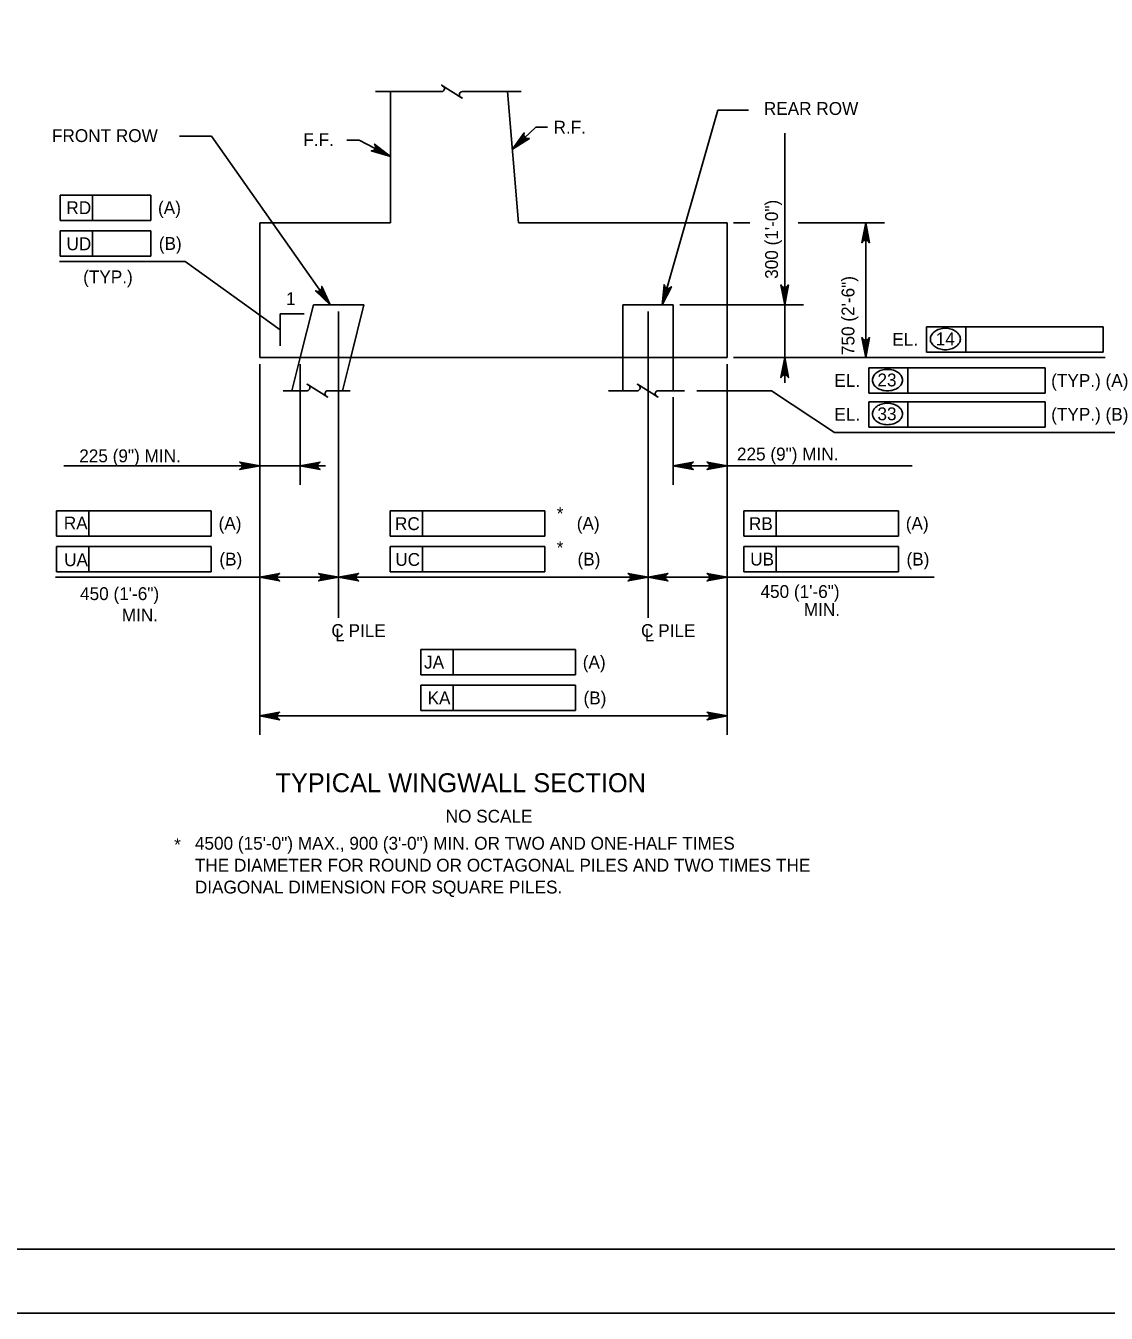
# Model space of a CAD drawing. Extents: x 638340 to 640241, y 295465 to 298435.
# Drawn here: x 639649.8 to 639902.2, y 295465.5 to 295766.2 of the extents above; entities that cross this region are included whole.
import ezdxf

# ---------------------------------------------------------------- set-up
doc = ezdxf.new("R2010")
doc.units = 0
for name, color, linetype in [('2', 7, 'Continuous'), ('4', 7, 'Continuous'), ('5', 7, 'Continuous'), ('PLT-BNDY', 7, 'Continuous')]:
    doc.layers.add(name, color=color, linetype=linetype)

msp = doc.modelspace()

# ---------------------------------------------------------------- linework, layer by layer
at = {"layer": '2'}
for p, q in [((639811.41, 295746.46), (639818.61, 295746.46)), ((639693.2, 295740.4), (639685.68, 295740.4)), ((639763.45, 295737.34), (639768.92, 295742.5)), ((639768.92, 295742.5), (639771.65, 295742.5)), ((639827.06, 295700.99), (639827.06, 295741.12)), ((639727.65, 295739.45), (639724.8, 295739.45)), ((639735.01, 295735.64), (639727.65, 295739.45)), ((639657.85, 295726.65), (639678.98, 295726.65)), ((639657.85, 295726.65), (639657.85, 295720.75)), ((639665.41, 295726.65), (639665.41, 295720.75)), ((639678.98, 295726.65), (639678.98, 295720.75)), ((639657.85, 295720.75), (639678.98, 295720.75)), ((639815.13, 295720.19), (639818.94, 295720.19)), ((639830.2, 295720.19), (639850.41, 295720.19)), ((639845.98, 295720.19), (639845.98, 295688.69)), ((639657.85, 295718.3), (639657.85, 295712.39)), ((639657.85, 295718.3), (639678.98, 295718.3)), ((639665.41, 295718.3), (639665.41, 295712.39)), ((639678.98, 295718.3), (639678.98, 295712.39)), ((639687.03, 295711.12), (639657.69, 295711.12)), ((639657.85, 295712.39), (639678.98, 295712.39)), ((639709.25, 295695.16), (639687.03, 295711.12)), ((639802.58, 295700.99), (639831.49, 295700.99)), ((639827.06, 295700.99), (639827.06, 295688.69)), ((639709.25, 295698.91), (639709.25, 295691.41)), ((639714.81, 295698.91), (639709.25, 295698.91)), ((639722.86, 295699.45), (639722.86, 295627.87)), ((639722.86, 295699.45), (639722.86, 295627.87)), ((639795.14, 295699.45), (639795.14, 295627.87)), ((639860.22, 295695.88), (639901.43, 295695.88)), ((639860.22, 295689.97), (639860.22, 295695.88)), ((639869.39, 295689.97), (639869.39, 295695.88)), ((639901.43, 295695.88), (639901.43, 295689.97)), ((639815.13, 295688.69), (639901.9, 295688.69)), ((639815.13, 295688.69), (639831.49, 295688.69)), ((639827.06, 295688.69), (639827.06, 295682.79)), ((639901.43, 295689.97), (639860.22, 295689.97)), ((639704.43, 295687.15), (639704.43, 295624.32)), ((639704.43, 295687.15), (639704.43, 295600.54)), ((639704.43, 295687.15), (639704.43, 295659)), ((639713.88, 295687.15), (639713.88, 295659)), ((639813.59, 295687.15), (639813.59, 295624.32)), ((639813.59, 295687.15), (639813.59, 295600.54)), ((639813.59, 295687.15), (639813.59, 295659)), ((639846.69, 295680.37), (639846.69, 295686.28)), ((639846.69, 295686.28), (639887.9, 295686.28)), ((639855.86, 295680.37), (639855.86, 295686.28)), ((639887.9, 295686.28), (639887.9, 295680.37)), ((639801.04, 295679.42), (639801.04, 295659)), ((639806.54, 295680.96), (639824.01, 295680.96)), ((639824.01, 295680.96), (639838.69, 295671.18)), ((639887.9, 295680.37), (639846.69, 295680.37)), ((639846.69, 295678.37), (639887.9, 295678.37)), ((639846.69, 295672.46), (639846.69, 295678.37)), ((639855.86, 295672.46), (639855.86, 295678.37)), ((639887.9, 295678.37), (639887.9, 295672.46)), ((639838.69, 295671.18), (639912.2, 295671.18)), ((639887.9, 295672.46), (639846.69, 295672.46)), ((639713.88, 295663.43), (639658.65, 295663.43)), ((639713.88, 295663.43), (639719.79, 295663.43)), ((639801.04, 295663.43), (639813.59, 295663.43)), ((639813.59, 295663.43), (639856.81, 295663.43)), ((639656.99, 295652.92), (639693.12, 295652.92)), ((639656.99, 295652.92), (639656.99, 295647.01)), ((639664.55, 295652.92), (639664.55, 295647.01)), ((639693.12, 295652.92), (639693.12, 295647.01)), ((639734.89, 295652.92), (639771.03, 295652.92)), ((639734.89, 295652.92), (639734.89, 295647.01)), ((639742.45, 295652.92), (639742.45, 295647.01)), ((639771.03, 295652.92), (639771.03, 295647.01)), ((639817.5, 295652.92), (639853.64, 295652.92)), ((639817.5, 295652.92), (639817.5, 295647.01)), ((639825.07, 295652.92), (639825.07, 295647.01)), ((639853.64, 295652.92), (639853.64, 295647.01)), ((639656.99, 295647.01), (639693.12, 295647.01)), ((639734.89, 295647.01), (639771.03, 295647.01)), ((639817.5, 295647.01), (639853.64, 295647.01)), ((639656.99, 295644.57), (639693.12, 295644.57)), ((639656.99, 295644.57), (639656.99, 295638.66)), ((639664.55, 295644.57), (639664.55, 295638.66)), ((639693.12, 295644.57), (639693.12, 295638.66)), ((639734.89, 295644.57), (639771.03, 295644.57)), ((639734.89, 295644.57), (639734.89, 295638.66)), ((639742.45, 295644.57), (639742.45, 295638.66)), ((639771.03, 295644.57), (639771.03, 295638.66)), ((639813.59, 295645.92), (639813.59, 295625.79)), ((639817.5, 295644.57), (639853.64, 295644.57)), ((639817.5, 295644.57), (639817.5, 295638.66)), ((639825.07, 295644.57), (639825.07, 295638.66)), ((639853.64, 295644.57), (639853.64, 295638.66)), ((639722.86, 295640.9), (639722.86, 295632.96)), ((639795.14, 295640.9), (639795.14, 295632.96)), ((639704.43, 295637.39), (639656.72, 295637.39)), ((639656.99, 295638.66), (639693.12, 295638.66)), ((639719.91, 295637.39), (639704.43, 295637.39)), ((639725.82, 295637.39), (639792.18, 295637.39)), ((639734.89, 295638.66), (639771.03, 295638.66)), ((639798.09, 295637.39), (639813.59, 295637.39)), ((639813.59, 295637.39), (639861.99, 295637.39)), ((639817.5, 295638.66), (639853.64, 295638.66)), ((639742.05, 295620.5), (639778.18, 295620.5)), ((639742.05, 295620.5), (639742.05, 295614.59)), ((639749.61, 295620.5), (639749.61, 295614.59)), ((639778.18, 295620.5), (639778.18, 295614.59)), ((639742.05, 295614.59), (639778.18, 295614.59)), ((639742.05, 295612.15), (639778.18, 295612.15)), ((639742.05, 295612.15), (639742.05, 295606.24)), ((639749.61, 295612.15), (639749.61, 295606.24)), ((639778.18, 295612.15), (639778.18, 295606.24)), ((639704.43, 295602.46), (639704.43, 295607.47)), ((639813.59, 295607.47), (639813.59, 295602.46)), ((639704.43, 295604.97), (639813.59, 295604.97)), ((639742.05, 295606.24), (639778.18, 295606.24)), ((640102.46, 295480.46), (639316.46, 295480.46))]:
    msp.add_line(p, q, dxfattribs=at)
for points in [[(639798.48, 295700.99), (639811.41, 295746.46)], [(639720.9, 295700.99), (639693.2, 295740.4)], [(639763.45, 295737.34), (639766.24, 295741.17), (639766.15, 295740.74), (639766.23, 295740.39), (639766.4, 295740.13), (639766.66, 295739.94), (639767.01, 295739.84), (639767.44, 295739.9), (639763.45, 295737.34), (639767.01, 295739.84), (639766.66, 295739.94), (639763.45, 295737.34), (639766.4, 295740.13), (639766.23, 295740.39), (639763.45, 295737.34), (639766.15, 295740.74)], [(639735.01, 295735.64), (639730.47, 295737.01), (639730.9, 295737.07), (639731.21, 295737.26), (639731.4, 295737.51), (639731.5, 295737.81), (639731.48, 295738.18), (639731.27, 295738.56), (639735.01, 295735.64), (639731.48, 295738.18), (639731.5, 295737.81), (639735.01, 295735.64), (639731.4, 295737.51), (639731.21, 295737.26), (639735.01, 295735.64), (639730.9, 295737.07)], [(639845.98, 295720.19), (639846.85, 295715.53), (639846.6, 295715.89), (639846.29, 295716.07), (639845.98, 295716.13), (639845.66, 295716.07), (639845.35, 295715.89), (639845.1, 295715.53), (639845.98, 295720.19), (639845.35, 295715.89), (639845.66, 295716.07), (639845.98, 295720.19), (639845.98, 295716.13), (639846.29, 295716.07), (639845.98, 295720.19), (639846.6, 295715.89)], [(639720.9, 295700.99), (639717.5, 295704.3), (639717.91, 295704.15), (639718.28, 295704.18), (639718.56, 295704.31), (639718.79, 295704.54), (639718.94, 295704.87), (639718.93, 295705.31), (639720.9, 295700.99), (639718.94, 295704.87), (639718.79, 295704.54), (639720.9, 295700.99), (639718.56, 295704.31), (639718.28, 295704.18), (639720.9, 295700.99), (639717.91, 295704.15)], [(639798.48, 295700.99), (639798.91, 295705.71), (639799.06, 295705.3), (639799.31, 295705.03), (639799.59, 295704.9), (639799.91, 295704.86), (639800.26, 295704.96), (639800.6, 295705.23), (639798.48, 295700.99), (639800.26, 295704.96), (639799.91, 295704.86), (639798.48, 295700.99), (639799.59, 295704.9), (639799.31, 295705.03), (639798.48, 295700.99), (639799.06, 295705.3)], [(639827.06, 295700.99), (639826.18, 295705.65), (639826.43, 295705.29), (639826.74, 295705.11), (639827.06, 295705.05), (639827.37, 295705.11), (639827.68, 295705.29), (639827.93, 295705.65), (639827.06, 295700.99), (639827.68, 295705.29), (639827.37, 295705.11), (639827.06, 295700.99), (639827.06, 295705.05), (639826.74, 295705.11), (639827.06, 295700.99), (639826.43, 295705.29)], [(639845.98, 295688.69), (639845.1, 295693.35), (639845.35, 295692.99), (639845.66, 295692.81), (639845.98, 295692.75), (639846.29, 295692.81), (639846.6, 295692.99), (639846.85, 295693.35), (639845.98, 295688.69), (639846.6, 295692.99), (639846.29, 295692.81), (639845.98, 295688.69), (639845.98, 295692.75), (639845.66, 295692.81), (639845.98, 295688.69), (639845.35, 295692.99)], [(639827.06, 295688.69), (639827.93, 295684.03), (639827.68, 295684.39), (639827.37, 295684.57), (639827.06, 295684.63), (639826.74, 295684.57), (639826.43, 295684.39), (639826.18, 295684.03), (639827.06, 295688.69), (639826.43, 295684.39), (639826.74, 295684.57), (639827.06, 295688.69), (639827.06, 295684.63), (639827.37, 295684.57), (639827.06, 295688.69), (639827.68, 295684.39)], [(639704.43, 295663.43), (639699.77, 295662.55), (639700.13, 295662.8), (639700.31, 295663.11), (639700.37, 295663.43), (639700.31, 295663.74), (639700.13, 295664.05), (639699.77, 295664.3), (639704.43, 295663.43), (639700.13, 295664.05), (639700.31, 295663.74), (639704.43, 295663.43), (639700.37, 295663.43), (639700.31, 295663.11), (639704.43, 295663.43), (639700.13, 295662.8)], [(639713.88, 295663.43), (639718.54, 295664.3), (639718.18, 295664.05), (639718, 295663.74), (639717.94, 295663.43), (639718, 295663.11), (639718.18, 295662.8), (639718.54, 295662.55), (639713.88, 295663.43), (639718.18, 295662.8), (639718, 295663.11), (639713.88, 295663.43), (639717.94, 295663.43), (639718, 295663.74), (639713.88, 295663.43), (639718.18, 295664.05)], [(639801.04, 295663.43), (639805.7, 295664.3), (639805.34, 295664.05), (639805.16, 295663.74), (639805.1, 295663.43), (639805.16, 295663.11), (639805.34, 295662.8), (639805.7, 295662.55), (639801.04, 295663.43), (639805.34, 295662.8), (639805.16, 295663.11), (639801.04, 295663.43), (639805.1, 295663.43), (639805.16, 295663.74), (639801.04, 295663.43), (639805.34, 295664.05)], [(639813.59, 295663.43), (639808.93, 295662.55), (639809.29, 295662.8), (639809.48, 295663.11), (639809.53, 295663.43), (639809.48, 295663.74), (639809.29, 295664.05), (639808.93, 295664.3), (639813.59, 295663.43), (639809.29, 295664.05), (639809.48, 295663.74), (639813.59, 295663.43), (639809.53, 295663.43), (639809.48, 295663.11), (639813.59, 295663.43), (639809.29, 295662.8)], [(639704.43, 295637.39), (639709.09, 295638.26), (639708.73, 295638.01), (639708.55, 295637.7), (639708.49, 295637.39), (639708.55, 295637.07), (639708.73, 295636.76), (639709.09, 295636.51), (639704.43, 295637.39), (639708.73, 295636.76), (639708.55, 295637.07), (639704.43, 295637.39), (639708.49, 295637.39), (639708.55, 295637.7), (639704.43, 295637.39), (639708.73, 295638.01)], [(639722.86, 295637.39), (639718.2, 295636.51), (639718.56, 295636.76), (639718.74, 295637.07), (639718.8, 295637.39), (639718.74, 295637.7), (639718.56, 295638.01), (639718.2, 295638.26), (639722.86, 295637.39), (639718.56, 295638.01), (639718.74, 295637.7), (639722.86, 295637.39), (639718.8, 295637.39), (639718.74, 295637.07), (639722.86, 295637.39), (639718.56, 295636.76)], [(639722.86, 295637.39), (639727.52, 295636.51), (639727.16, 295636.76), (639726.98, 295637.07), (639726.92, 295637.39), (639726.98, 295637.7), (639727.16, 295638.01), (639727.52, 295638.26), (639722.86, 295637.39), (639727.16, 295638.01), (639726.98, 295637.7), (639722.86, 295637.39), (639726.92, 295637.39), (639726.98, 295637.07), (639722.86, 295637.39), (639727.16, 295636.76)], [(639795.14, 295637.39), (639790.47, 295636.51), (639790.83, 295636.76), (639791.02, 295637.07), (639791.07, 295637.39), (639791.02, 295637.7), (639790.83, 295638.01), (639790.47, 295638.26), (639795.14, 295637.39), (639790.83, 295638.01), (639791.02, 295637.7), (639795.14, 295637.39), (639791.07, 295637.39), (639791.02, 295637.07), (639795.14, 295637.39), (639790.83, 295636.76)], [(639795.14, 295637.39), (639799.8, 295636.51), (639799.44, 295636.76), (639799.25, 295637.07), (639799.2, 295637.39), (639799.25, 295637.7), (639799.44, 295638.01), (639799.8, 295638.26), (639795.14, 295637.39), (639799.44, 295638.01), (639799.25, 295637.7), (639795.14, 295637.39), (639799.2, 295637.39), (639799.25, 295637.07), (639795.14, 295637.39), (639799.44, 295636.76)], [(639813.59, 295637.39), (639808.93, 295636.51), (639809.29, 295636.76), (639809.48, 295637.07), (639809.53, 295637.39), (639809.48, 295637.7), (639809.29, 295638.01), (639808.93, 295638.26), (639813.59, 295637.39), (639809.29, 295638.01), (639809.48, 295637.7), (639813.59, 295637.39), (639809.53, 295637.39), (639809.48, 295637.07), (639813.59, 295637.39), (639809.29, 295636.76)], [(639704.43, 295604.97), (639709.09, 295605.84), (639708.73, 295605.59), (639708.55, 295605.28), (639708.49, 295604.97), (639708.55, 295604.65), (639708.73, 295604.34), (639709.09, 295604.09), (639704.43, 295604.97), (639708.73, 295604.34), (639708.55, 295604.65), (639704.43, 295604.97), (639708.49, 295604.97), (639708.55, 295605.28), (639704.43, 295604.97), (639708.73, 295605.59)], [(639813.59, 295604.97), (639808.93, 295604.09), (639809.29, 295604.34), (639809.48, 295604.65), (639809.53, 295604.97), (639809.48, 295605.28), (639809.29, 295605.59), (639808.93, 295605.84), (639813.59, 295604.97), (639809.29, 295605.59), (639809.48, 295605.28), (639813.59, 295604.97), (639809.53, 295604.97), (639809.48, 295604.65), (639813.59, 295604.97), (639809.29, 295604.34)]]:
    msp.add_lwpolyline(points, dxfattribs=at)
for points in [[(639765.94, 295739.01), (639765.26, 295739.72), (639763.45, 295737.34)], [(639732.61, 295737.44), (639732.16, 295736.56), (639735.01, 295735.64)], [(639845.49, 295717.24), (639846.47, 295717.24), (639845.98, 295720.19)], [(639720.9, 295700.99), (639719.4, 295703.55), (639719, 295703.27)], [(639798.48, 295700.99), (639799.53, 295703.76), (639799.05, 295703.9)], [(639826.57, 295703.94), (639827.55, 295703.94), (639827.06, 295700.99)], [(639845.49, 295691.65), (639846.47, 295691.65), (639845.98, 295688.69)], [(639826.57, 295685.74), (639827.55, 295685.74), (639827.06, 295688.69)], [(639701.48, 295663.92), (639701.48, 295662.93), (639704.43, 295663.43)], [(639716.83, 295663.92), (639716.83, 295662.93), (639713.88, 295663.43)], [(639803.99, 295663.92), (639803.99, 295662.93), (639801.04, 295663.43)], [(639810.64, 295663.92), (639810.64, 295662.93), (639813.59, 295663.43)], [(639719.91, 295637.88), (639719.91, 295636.89), (639722.86, 295637.39)], [(639725.82, 295637.88), (639725.82, 295636.89), (639722.86, 295637.39)], [(639792.18, 295637.88), (639792.18, 295636.89), (639795.14, 295637.39)], [(639798.09, 295637.88), (639798.09, 295636.89), (639795.14, 295637.39)], [(639810.64, 295637.88), (639810.64, 295636.89), (639813.59, 295637.39)]]:
    msp.add_lwpolyline(points, close=True, dxfattribs=at)
for centre, radius, start, end in [((639863.72, 295692.57), 2.76, 125.6316, 149.9767), ((639864.25, 295691.83), 3.66, 106.5358, 125.6316), ((639864.6, 295690.67), 4.87, 90, 106.5358), ((639864.6, 295690.67), 4.87, 73.4642, 90), ((639864.94, 295691.83), 3.66, 54.3684, 73.4642), ((639865.47, 295692.57), 2.76, 30.0233, 54.3684), ((639862.92, 295693.03), 1.83, 149.9767, 180), ((639862.92, 295693.03), 1.83, 180, 210.0233), ((639863.72, 295693.5), 2.76, 210.0233, 234.3684), ((639865.47, 295693.5), 2.76, 305.6316, 329.9767), ((639866.27, 295693.03), 1.83, 0, 30.0233), ((639866.27, 295693.03), 1.83, 329.9767, 0), ((639864.25, 295694.23), 3.66, 234.3684, 253.4642), ((639864.6, 295695.39), 4.87, 253.4642, 270), ((639864.6, 295695.39), 4.87, 270, 286.5358), ((639864.94, 295694.23), 3.66, 286.5358, 305.6316), ((639850.72, 295682.23), 3.66, 106.5358, 125.6316), ((639851.07, 295681.07), 4.87, 90, 106.5358), ((639851.07, 295681.07), 4.87, 73.4642, 90), ((639851.41, 295682.23), 3.66, 54.3684, 73.4642), ((639849.39, 295683.43), 1.83, 149.9767, 180), ((639849.39, 295683.43), 1.83, 180, 210.0233), ((639850.19, 295682.96), 2.76, 125.6316, 149.9767), ((639850.19, 295683.89), 2.76, 210.0233, 234.3684), ((639851.94, 295682.96), 2.76, 30.0233, 54.3684), ((639851.94, 295683.89), 2.76, 305.6316, 329.9767), ((639852.74, 295683.43), 1.83, 0, 30.0233), ((639852.74, 295683.43), 1.83, 329.9767, 0), ((639850.72, 295684.63), 3.66, 234.3684, 253.4642), ((639851.07, 295685.79), 4.87, 253.4642, 270), ((639851.07, 295685.79), 4.87, 270, 286.5358), ((639851.41, 295684.63), 3.66, 286.5358, 305.6316), ((639849.39, 295675.52), 1.83, 149.9767, 180), ((639850.19, 295675.06), 2.76, 125.6316, 149.9767), ((639850.72, 295674.32), 3.66, 106.5358, 125.6316), ((639851.07, 295673.16), 4.87, 90, 106.5358), ((639851.07, 295673.16), 4.87, 73.4642, 90), ((639851.41, 295674.32), 3.66, 54.3684, 73.4642), ((639851.94, 295675.06), 2.76, 30.0233, 54.3684), ((639852.74, 295675.52), 1.83, 0, 30.0233), ((639849.39, 295675.52), 1.83, 180, 210.0233), ((639850.19, 295675.99), 2.76, 210.0233, 234.3684), ((639850.72, 295676.72), 3.66, 234.3684, 253.4642), ((639851.41, 295676.72), 3.66, 286.5358, 305.6316), ((639851.94, 295675.99), 2.76, 305.6316, 329.9767), ((639852.74, 295675.52), 1.83, 329.9767, 0), ((639851.07, 295677.88), 4.87, 253.4642, 270), ((639851.07, 295677.88), 4.87, 270, 286.5358)]:
    msp.add_arc(centre, radius, start, end, dxfattribs=at)
at = {"layer": '4'}
for p, q in [((639746.94, 295750.82), (639731.48, 295750.82)), ((639735.01, 295720.19), (639735.01, 295750.82)), ((639765.47, 295750.82), (639751.79, 295750.82)), ((639762.33, 295750.82), (639764.88, 295720.19)), ((639704.43, 295720.19), (639704.43, 295688.69)), ((639735.01, 295720.19), (639704.43, 295720.19)), ((639813.59, 295720.19), (639764.88, 295720.19)), ((639813.59, 295688.69), (639813.59, 295720.19)), ((639813.59, 295688.69), (639704.43, 295688.69))]:
    msp.add_line(p, q, dxfattribs=at)
msp.add_lwpolyline([(639751.44, 295749.49), (639751.74, 295749.31), (639746.93, 295752.33), (639747.25, 295752.13)], dxfattribs=at)
for centre, start, end in [((639746.87, 295751.53), 275.3286, 57.8672), ((639751.79, 295750.11), 90, 240)]:
    msp.add_arc(centre, 0.71, start, end, dxfattribs=at)
at = {"layer": '5'}
for p, q in [((639713.88, 295688.69), (639716.96, 295700.99)), ((639728.77, 295700.99), (639716.96, 295700.99)), ((639725.69, 295688.69), (639728.77, 295700.99)), ((639789.23, 295688.69), (639789.23, 295700.99)), ((639801.04, 295700.99), (639789.23, 295700.99)), ((639801.04, 295688.69), (639801.04, 295700.99)), ((639711.95, 295680.96), (639713.88, 295688.69)), ((639723.76, 295680.96), (639725.69, 295688.69)), ((639789.23, 295680.96), (639789.23, 295688.69)), ((639801.04, 295680.96), (639801.04, 295688.69)), ((639715.52, 295680.96), (639709.92, 295680.96)), ((639725.57, 295680.96), (639720.38, 295680.96)), ((639792.67, 295680.96), (639785.93, 295680.96)), ((639803.67, 295680.96), (639797.52, 295680.96))]:
    msp.add_line(p, q, dxfattribs=at)
for points in [[(639720.02, 295679.63), (639720.33, 295679.45), (639715.51, 295682.47), (639715.84, 295682.27)], [(639797.17, 295679.63), (639797.47, 295679.45), (639792.66, 295682.47), (639792.98, 295682.27)]]:
    msp.add_lwpolyline(points, dxfattribs=at)
for centre, start, end in [((639715.46, 295681.67), 275.3286, 57.8672), ((639720.38, 295680.25), 90, 240), ((639792.6, 295681.67), 275.3286, 57.8672), ((639797.52, 295680.25), 90, 240)]:
    msp.add_arc(centre, 0.71, start, end, dxfattribs=at)
at = {"layer": 'PLT-BNDY'}
msp.add_lwpolyline([(639276.46, 296059.46), (640117.46, 296059.46), (640117.46, 295465.46), (639276.46, 295465.46)], close=True, dxfattribs=at)

# ---------------------------------------------------------------- texts
at = {"layer": '2'}
for s, height, p in [('REAR ROW', 3, (639822.19, 295745.38)), ('R.F.', 3, (639773.07, 295741.01)), ('FRONT ROW', 3, (639655.9, 295739.04)), ('F.F.', 3, (639714.62, 295738.09)), ('1', 3, (639710.59, 295700.95)), ('EL.', 3, (639852.2, 295691.46)), ('14', 3, (639862.35, 295691.57)), ('EL.', 3, (639838.67, 295681.85)), ('23', 3, (639848.73, 295681.97)), ('(TYP.) (A)', 3, (639889.31, 295681.85)), ('EL.', 3, (639838.67, 295673.95)), ('33', 3, (639848.73, 295674.06)), ('(TYP.) (B)', 3, (639889.31, 295673.95)), ('225 (9") MIN.', 3.0001, (639662.28, 295664.24)), ('225 (9") MIN.', 3.0001, (639815.91, 295664.66)), ('450 (1\'-6")', 3.0001, (639662.47, 295632.05)), ('450 (1\'-6")', 3.0001, (639821.41, 295632.55)), ('MIN.', 3, (639831.53, 295628.36)), ('MIN.', 3, (639672.21, 295627.05)), ('C PILE', 3, (639721.17, 295623.42)), ('L', 3, (639722.06, 295622.4)), ('C PILE', 3, (639793.51, 295623.42)), ('L', 3, (639794.39, 295622.4)), ('NO SCALE', 3, (639747.87, 295580.06)), ('4500 (15\'-0") MAX., 900 (3\'-0") MIN. OR TWO AND ONE-HALF TIMES', 3.0001, (639689.29, 295573.74)), ('THE DIAMETER FOR ROUND OR OCTAGONAL PILES AND TWO TIMES THE', 3.0001, (639689.29, 295568.62)), ('DIAGONAL DIMENSION FOR SQUARE PILES.', 3.0001, (639689.29, 295563.51))]:
    msp.add_text(s, height=height, dxfattribs=at).set_placement(p)
for s, height, rotation, p in [('RD', 3, 359.9382, (639659.27, 295722.2)), ('(A)', 3, 359.9382, (639680.68, 295722.2)), ('300 (1\'-0")', 3.0001, 90, (639825.5, 295707.08)), ('UD', 3, 359.9382, (639659.29, 295713.77)), ('(B)', 3, 359.9382, (639680.86, 295713.85)), ('(TYP.)', 3, 359.9382, (639663.19, 295706.05)), ('750 (2\'-6")', 3.0001, 90, (639843.35, 295689.27)), ('*', 3, 359.9382, (639773.81, 295650.76)), ('RA', 3, 359.9382, (639658.67, 295648.54)), ('(A)', 3, 359.9382, (639694.83, 295648.47)), ('RC', 3, 359.9382, (639736.02, 295648.4)), ('(A)', 3, 359.9382, (639778.49, 295648.47)), ('RB', 3, 359.9382, (639818.71, 295648.4)), ('(A)', 3, 359.9382, (639855.35, 295648.47)), ('(B)', 3, 359.9382, (639695.01, 295640.12)), ('*', 3, 359.9382, (639773.81, 295642.8)), ('(B)', 3, 359.9382, (639778.67, 295640.12)), ('(B)', 3, 359.9382, (639855.52, 295640.12)), ('UA', 3, 359.9382, (639658.75, 295639.97)), ('UC', 3, 359.9382, (639736.1, 295640.04)), ('UB', 3, 359.9382, (639819.01, 295640.12)), ('(A)', 3, 359.9382, (639779.89, 295616.05)), ('JA', 3, 359.9382, (639742.83, 295616.05)), ('KA', 3, 359.9382, (639743.64, 295607.7)), ('(B)', 3, 359.9382, (639780.07, 295607.7)), ('*', 3, 359.9382, (639684.44, 295573.42))]:
    msp.add_text(s, height=height, rotation=rotation, dxfattribs=at).set_placement(p)
at = {"layer": '4'}
msp.add_text('TYPICAL WINGWALL SECTION', height=4.4294, dxfattribs=at).set_placement((639708.1, 295587.16))

doc.saveas('drawing.dxf')
